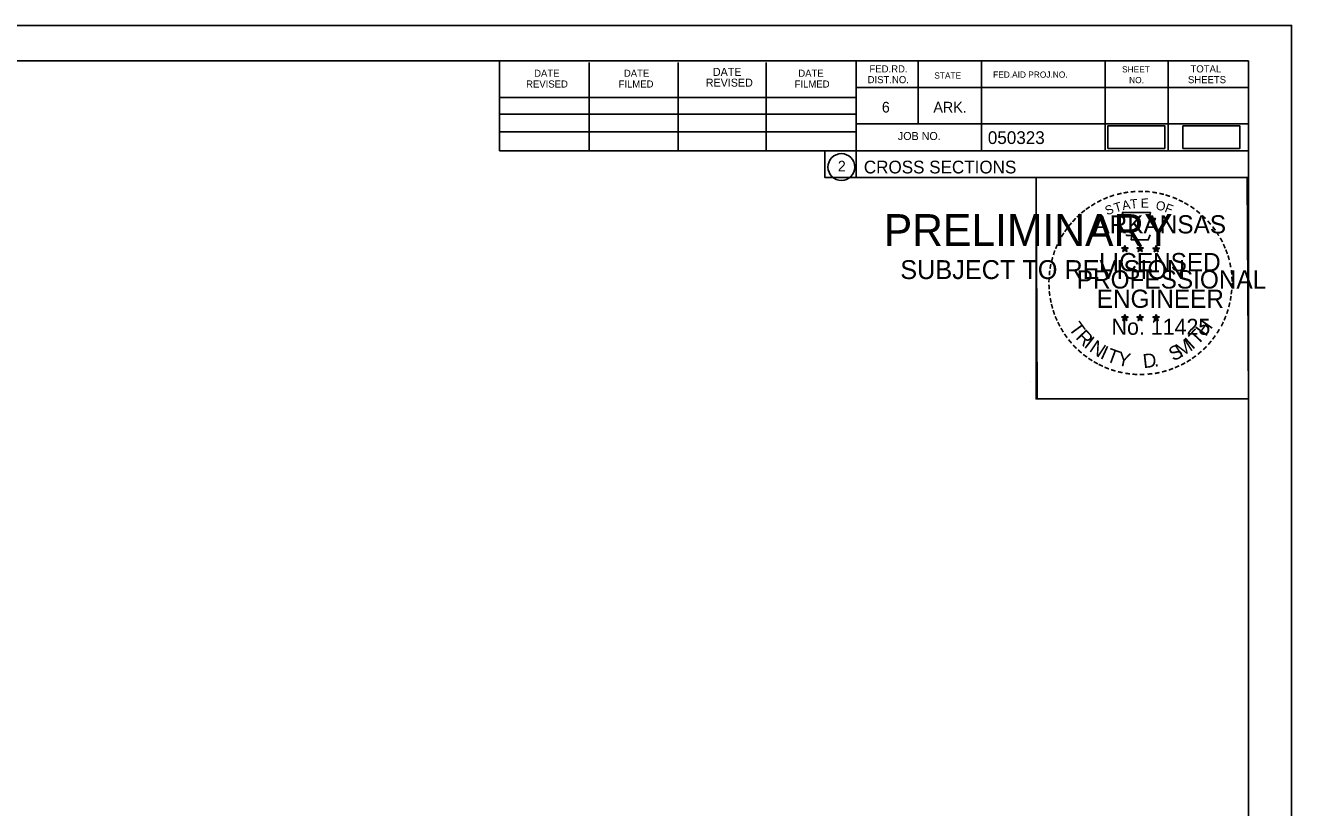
# Model space of a CAD drawing. Extents: x 1360146 to 1361431, y 631444 to 632352.
# Drawn here: x 1360340.6 to 1360479.7, y 632211.6 to 632297.5 of the extents above; entities that cross this region are included whole.
import ezdxf

# ---------------------------------------------------------------- set-up
doc = ezdxf.new("R2010")
doc.units = 0
for name, color, linetype in [('Default', 7, 'Continuous'), ('R_Border', 7, 'Continuous'), ('R_Border PE', 7, 'Continuous'), ('R_Border Prem', 7, 'Continuous'), ('R_No Plot', 7, 'Continuous')]:
    doc.layers.add(name, color=color, linetype=linetype)

msp = doc.modelspace()

# ---------------------------------------------------------------- linework, layer by layer
at = {"layer": 'Default'}
for points in [[(1360459.52, 632284), (1360465.77, 632284), (1360465.77, 632286.48), (1360459.52, 632286.48)], [(1360467.76, 632283.99), (1360474.01, 632283.99), (1360474.01, 632286.46), (1360467.76, 632286.46)]]:
    msp.add_lwpolyline(points, close=True, dxfattribs=at)
at = {"layer": 'R_Border'}
for p, q in [((1360158.77, 632293.62), (1360474.95, 632293.62)), ((1360392.69, 632283.74), (1360392.69, 632293.62)), ((1360431.85, 632293.62), (1360431.85, 632280.82)), ((1360438.69, 632293.62), (1360438.69, 632286.68)), ((1360445.63, 632293.62), (1360445.63, 632283.74)), ((1360459.21, 632293.62), (1360459.21, 632283.74)), ((1360466.15, 632293.62), (1360466.15, 632283.74)), ((1360474.95, 632088.16), (1360474.95, 632293.62)), ((1360402.55, 632283.74), (1360402.55, 632293.42)), ((1360412.31, 632283.74), (1360412.31, 632293.42)), ((1360421.99, 632283.74), (1360421.99, 632293.42)), ((1360392.69, 632289.6), (1360431.85, 632289.6)), ((1360474.95, 632290.68), (1360431.85, 632290.68)), ((1360474.95, 632290.7), (1360474.95, 632290.7)), ((1360392.69, 632287.74), (1360431.85, 632287.74)), ((1360474.95, 632286.68), (1360431.85, 632286.68)), ((1360434.81, 632286.68), (1360474.95, 632286.68)), ((1360392.69, 632283.74), (1360392.69, 632285.8)), ((1360392.69, 632285.8), (1360431.85, 632285.8)), ((1360474.95, 632283.74), (1360392.69, 632283.74)), ((1360431.85, 632280.82), (1360474.95, 632280.82))]:
    msp.add_line(p, q, dxfattribs=at)
msp.add_circle((1360430.24, 632281.95), 1.47, dxfattribs=at)
at = {"layer": 'R_Border PE'}
for p, q in [((1360461.04, 632273.07), (1360461.38, 632272.96)), ((1360461.04, 632273.07), (1360461.29, 632273.03)), ((1360461.04, 632273.07), (1360461.27, 632272.95)), ((1360461.17, 632272.67), (1360461.38, 632272.96)), ((1360461.17, 632272.67), (1360461.29, 632272.91)), ((1360461.17, 632272.67), (1360461.38, 632272.88)), ((1360461.38, 632273.33), (1360461.34, 632273.08)), ((1360461.38, 632272.96), (1360461.38, 632273.33)), ((1360461.38, 632273.33), (1360461.43, 632273.08)), ((1360461.73, 632273.07), (1360461.38, 632272.96)), ((1360461.6, 632272.67), (1360461.38, 632272.96)), ((1360461.6, 632272.67), (1360461.38, 632272.88)), ((1360461.73, 632273.07), (1360461.45, 632273.02)), ((1360461.6, 632272.67), (1360461.46, 632272.96)), ((1360461.73, 632273.07), (1360461.53, 632272.97)), ((1360462.71, 632273.07), (1360463.05, 632272.96)), ((1360462.71, 632273.07), (1360462.96, 632273.03)), ((1360462.71, 632273.07), (1360462.94, 632272.95)), ((1360462.84, 632272.67), (1360463.05, 632272.96)), ((1360462.84, 632272.67), (1360462.96, 632272.91)), ((1360462.84, 632272.67), (1360463.05, 632272.88)), ((1360463.05, 632273.33), (1360463.01, 632273.08)), ((1360463.05, 632272.96), (1360463.05, 632273.33)), ((1360463.05, 632273.33), (1360463.1, 632273.08)), ((1360463.4, 632273.07), (1360463.05, 632272.96)), ((1360463.27, 632272.67), (1360463.05, 632272.96)), ((1360463.27, 632272.67), (1360463.05, 632272.88)), ((1360463.4, 632273.07), (1360463.12, 632273.02)), ((1360463.27, 632272.67), (1360463.13, 632272.96)), ((1360463.4, 632273.07), (1360463.2, 632272.97)), ((1360464.47, 632273.06), (1360464.82, 632272.95)), ((1360464.47, 632273.06), (1360464.72, 632273.02)), ((1360464.47, 632273.06), (1360464.71, 632272.94)), ((1360464.6, 632272.65), (1360464.82, 632272.95)), ((1360464.6, 632272.65), (1360464.73, 632272.9)), ((1360464.6, 632272.65), (1360464.82, 632272.87)), ((1360464.82, 632273.32), (1360464.78, 632273.06)), ((1360464.82, 632272.95), (1360464.82, 632273.32)), ((1360464.82, 632273.32), (1360464.87, 632273.07)), ((1360465.17, 632273.06), (1360464.82, 632272.95)), ((1360465.03, 632272.65), (1360464.82, 632272.95)), ((1360465.03, 632272.65), (1360464.82, 632272.87)), ((1360465.17, 632273.06), (1360464.88, 632273.01)), ((1360465.03, 632272.65), (1360464.89, 632272.94)), ((1360465.17, 632273.06), (1360464.96, 632272.96)), ((1360461.03, 632265.5), (1360461.38, 632265.39)), ((1360461.03, 632265.5), (1360461.28, 632265.46)), ((1360461.03, 632265.5), (1360461.27, 632265.38)), ((1360461.16, 632265.09), (1360461.38, 632265.39)), ((1360461.16, 632265.09), (1360461.29, 632265.34)), ((1360461.16, 632265.09), (1360461.38, 632265.31)), ((1360461.38, 632265.75), (1360461.34, 632265.5)), ((1360461.38, 632265.39), (1360461.38, 632265.75)), ((1360461.38, 632265.75), (1360461.43, 632265.5)), ((1360461.73, 632265.5), (1360461.38, 632265.39)), ((1360461.59, 632265.09), (1360461.38, 632265.39)), ((1360461.59, 632265.09), (1360461.38, 632265.31)), ((1360461.73, 632265.5), (1360461.44, 632265.45)), ((1360461.59, 632265.09), (1360461.46, 632265.38)), ((1360461.73, 632265.5), (1360461.52, 632265.4)), ((1360462.7, 632265.5), (1360463.05, 632265.39)), ((1360462.7, 632265.5), (1360462.95, 632265.46)), ((1360462.7, 632265.5), (1360462.94, 632265.38)), ((1360462.83, 632265.09), (1360463.05, 632265.39)), ((1360462.83, 632265.09), (1360462.96, 632265.34)), ((1360462.83, 632265.09), (1360463.05, 632265.31)), ((1360463.05, 632265.75), (1360463.01, 632265.5)), ((1360463.05, 632265.39), (1360463.05, 632265.75)), ((1360463.05, 632265.75), (1360463.1, 632265.5)), ((1360463.4, 632265.5), (1360463.05, 632265.39)), ((1360463.26, 632265.09), (1360463.05, 632265.39)), ((1360463.26, 632265.09), (1360463.05, 632265.31)), ((1360463.4, 632265.5), (1360463.11, 632265.45)), ((1360463.26, 632265.09), (1360463.13, 632265.38)), ((1360463.4, 632265.5), (1360463.19, 632265.4)), ((1360464.47, 632265.49), (1360464.82, 632265.38)), ((1360464.47, 632265.49), (1360464.72, 632265.45)), ((1360464.47, 632265.49), (1360464.7, 632265.37)), ((1360464.6, 632265.08), (1360464.82, 632265.38)), ((1360464.6, 632265.08), (1360464.73, 632265.33)), ((1360464.6, 632265.08), (1360464.81, 632265.3)), ((1360464.82, 632265.74), (1360464.78, 632265.49)), ((1360465.03, 632265.08), (1360464.81, 632265.3)), ((1360464.82, 632265.38), (1360464.82, 632265.74)), ((1360464.82, 632265.74), (1360464.87, 632265.49)), ((1360465.16, 632265.49), (1360464.82, 632265.38)), ((1360465.03, 632265.08), (1360464.82, 632265.38)), ((1360465.16, 632265.49), (1360464.88, 632265.44)), ((1360465.03, 632265.08), (1360464.89, 632265.37)), ((1360465.16, 632265.49), (1360464.96, 632265.39))]:
    msp.add_line(p, q, dxfattribs=at)
for points in [[(1360461.08, 632276.95), (1360461.35, 632276.12)], [(1360464.59, 632276.03), (1360464.73, 632276.31), (1360464.04, 632276.29), (1360464.19, 632276.95), (1360461.08, 632276.95)], [(1360461.57, 632274.53), (1360461.57, 632274.44), (1360462.13, 632274.42), (1360462.08, 632273.95), (1360463.95, 632273.95), (1360464.15, 632274.49)], [(1360461.38, 632273.33), (1360461.6, 632272.67), (1360461.04, 632273.07), (1360461.73, 632273.07), (1360461.17, 632272.67), (1360461.38, 632273.33)], [(1360463.05, 632273.33), (1360463.27, 632272.67), (1360462.71, 632273.07), (1360463.4, 632273.07), (1360462.84, 632272.67), (1360463.05, 632273.33)], [(1360464.82, 632273.32), (1360465.03, 632272.65), (1360464.47, 632273.06), (1360465.17, 632273.06), (1360464.6, 632272.65), (1360464.82, 632273.32)], [(1360461.38, 632265.75), (1360461.59, 632265.09), (1360461.03, 632265.5), (1360461.73, 632265.5), (1360461.16, 632265.09), (1360461.38, 632265.75)], [(1360463.05, 632265.75), (1360463.26, 632265.09), (1360462.7, 632265.5), (1360463.4, 632265.5), (1360462.83, 632265.09), (1360463.05, 632265.75)], [(1360464.82, 632265.74), (1360465.03, 632265.08), (1360464.47, 632265.49), (1360465.16, 632265.49), (1360464.6, 632265.08), (1360464.82, 632265.74)]]:
    msp.add_lwpolyline(points, dxfattribs=at)
for centre, radius in [((1360461.38, 632272.96), 0.172), ((1360461.38, 632272.96), 0.145), ((1360461.38, 632272.96), 0.116), ((1360461.38, 632272.96), 0.0991), ((1360461.38, 632272.96), 0.0747), ((1360461.38, 632272.96), 0.0495), ((1360461.38, 632272.96), 0.0296), ((1360463.05, 632272.96), 0.172), ((1360463.05, 632272.96), 0.145), ((1360463.05, 632272.96), 0.116), ((1360463.05, 632272.96), 0.0991), ((1360463.05, 632272.96), 0.0747), ((1360463.05, 632272.96), 0.0495), ((1360463.05, 632272.96), 0.0296), ((1360464.82, 632272.95), 0.172), ((1360464.82, 632272.95), 0.145), ((1360464.82, 632272.95), 0.116), ((1360464.82, 632272.95), 0.0991), ((1360464.82, 632272.95), 0.0747), ((1360464.82, 632272.95), 0.0495), ((1360464.82, 632272.95), 0.0296), ((1360461.38, 632265.39), 0.172), ((1360461.38, 632265.39), 0.145), ((1360461.38, 632265.39), 0.116), ((1360461.38, 632265.39), 0.0991), ((1360461.38, 632265.39), 0.0747), ((1360461.38, 632265.39), 0.0495), ((1360461.38, 632265.39), 0.0296), ((1360463.05, 632265.39), 0.172), ((1360463.05, 632265.39), 0.145), ((1360463.05, 632265.39), 0.116), ((1360463.05, 632265.39), 0.0991), ((1360463.05, 632265.39), 0.0747), ((1360463.05, 632265.39), 0.0495), ((1360463.05, 632265.39), 0.0296), ((1360464.82, 632265.38), 0.172), ((1360464.82, 632265.38), 0.145), ((1360464.82, 632265.38), 0.116), ((1360464.82, 632265.38), 0.0991), ((1360464.82, 632265.38), 0.0747), ((1360464.82, 632265.38), 0.0495), ((1360464.82, 632265.38), 0.0296)]:
    msp.add_circle(centre, radius, dxfattribs=at)
at = {"layer": 'R_No Plot'}
for p, q in [((1360146.37, 632297.51), (1360479.7, 632297.51)), ((1360450.99, 632258.36), (1360450.99, 632258.36))]:
    msp.add_line(p, q, dxfattribs=at)
for points in [[(1360146.36, 632297.51), (1360479.7, 632297.51), (1360479.7, 632084.17), (1360146.36, 632084.17)], [(1360392.69, 632293.62), (1360392.69, 632283.74), (1360428.42, 632283.74), (1360428.42, 632280.82), (1360451.62, 632280.82), (1360451.62, 632256.49), (1360474.95, 632256.49), (1360474.95, 632088.16), (1360158.77, 632088.16), (1360158.77, 632293.62)], [(1360451.62, 632280.82), (1360474.83, 632280.82), (1360474.95, 632256.49), (1360451.74, 632256.49)]]:
    msp.add_lwpolyline(points, close=True, dxfattribs=at)

# ---------------------------------------------------------------- texts
at = {"layer": 'R_Border'}
for s, height, p in [('DATE', 0.782, (1360396.49, 632291.86)), ('DATE', 0.782, (1360406.35, 632291.86)), ('DATE', 0.879, (1360416.13, 632291.96)), ('DATE', 0.782, (1360425.51, 632291.86)), ('FED.RD.', 0.782, (1360433.33, 632292.34)), ('STATE', 0.684, (1360440.45, 632291.66)), ('FED.AID PROJ.NO.', 0.684, (1360446.91, 632291.76)), ('SHEET', 0.684, (1360461.07, 632292.34)), ('TOTAL', 0.782, (1360468.59, 632292.34)), ('REVISED', 0.782, (1360395.61, 632290.68)), ('FILMED', 0.782, (1360405.77, 632290.68)), ('REVISED', 0.879, (1360415.35, 632290.78)), ('FILMED', 0.782, (1360425.11, 632290.68)), ('DIST.NO.', 0.782, (1360433.13, 632291.16)), ('NO.', 0.684, (1360461.85, 632291.16)), ('SHEETS', 0.782, (1360468.31, 632291.16)), ('6', 1.17, (1360434.69, 632287.94)), ('ARK.', 1.172, (1360440.35, 632287.94)), ('JOB NO.', 0.879, (1360436.45, 632284.92)), ('050323', 1.4, (1360446.33, 632284.48)), ('2', 1.17, (1360429.85, 632281.47)), ('CROSS SECTIONS', 1.4, (1360432.71, 632281.25))]:
    msp.add_text(s, height=height, rotation=360, dxfattribs=at).set_placement(p)
at = {"layer": 'R_Border PE'}
for s, height, rotation, p in [('-', 1.6, 28.7918, (1360458.56, 632277.49)), ('-', 1.6, 24.3072, (1360459.19, 632277.81)), ('-', 1.6, 19.1761, (1360459.82, 632278.08)), ('-', 1.6, 13.6301, (1360460.57, 632278.32)), ('A', 1, 11.2132, (1360461.17, 632277.21)), ('-', 1.6, 10.2193, (1360461.25, 632278.48)), ('T', 1, 6.0228, (1360462.02, 632277.38)), ('-', 1.6, 5.8968, (1360461.98, 632278.59)), ('-', 1.6, 0.1862, (1360462.75, 632278.66)), ('E', 1, 0.8323, (1360463.13, 632277.49)), ('-', 1.6, 357.743, (1360463.48, 632278.65)), ('-', 1.6, 352.1617, (1360464.22, 632278.59)), ('-', 1.6, 347.2049, (1360464.94, 632278.48)), ('-', 1.6, 342.3362, (1360465.57, 632278.33)), ('-', 1.6, 337.8551, (1360466.31, 632278.1)), ('-', 1.6, 334.1211, (1360466.94, 632277.83)), ('-', 1.6, 38.9507, (1360456.91, 632276.35)), ('-', 1.6, 36.2317, (1360457.38, 632276.73)), ('-', 1.6, 34.0636, (1360457.96, 632277.12)), ('S', 1, 21.594, (1360459.43, 632276.63)), ('T', 1, 16.4036, (1360460.35, 632276.96)), ('O', 1, 350.4515, (1360464.73, 632277.28)), ('F', 1, 340.0707, (1360465.68, 632277.05)), ('-', 1.6, 329.6409, (1360467.52, 632277.55)), ('-', 1.6, 325.8627, (1360468.16, 632277.19)), ('-', 1.6, 320.5297, (1360468.77, 632276.76)), ('-', 1.6, 50.6142, (1360455.62, 632274.97)), ('-', 1.6, 48.423, (1360456.03, 632275.45)), ('-', 1.6, 42.9622, (1360456.47, 632275.93)), ('ARKANSAS', 2, 360, (1360457.93, 632274.66)), ('-', 1.6, 315.5786, (1360469.37, 632276.27)), ('-', 1.6, 309.8797, (1360469.94, 632275.72)), ('-', 1.6, 62.8713, (1360454.57, 632273.26)), ('-', 1.6, 58.0706, (1360454.88, 632273.87)), ('-', 1.6, 54.2325, (1360455.21, 632274.4)), ('-', 1.6, 306.6522, (1360470.47, 632275.12)), ('-', 1.4, 303.6753, (1360470.95, 632274.55)), ('-', 1.6, 299.6684, (1360471.27, 632273.95)), ('-', 1.6, 72.3945, (1360454.09, 632272.02)), ('-', 1.6, 67.7743, (1360454.31, 632272.65)), ('DWB', 0.01, 360, (1360461.37, 632272.96)), ('DWB', 0.01, 360, (1360463.04, 632272.96)), ('DWB', 0.01, 360, (1360464.81, 632272.95)), ('-', 1.6, 294.6628, (1360471.59, 632273.33)), ('-', 1.6, 290.5728, (1360471.85, 632272.76)), ('-', 1.6, 75.461, (1360453.9, 632271.31)), ('LICENSED', 2, 360, (1360458.53, 632270.51)), ('-', 1.6, 285.1233, (1360472.09, 632272.18)), ('-', 1.6, 280.5493, (1360472.29, 632271.44)), ('-', 1.6, 85.1863, (1360453.69, 632269.9)), ('-', 1.6, 81.2013, (1360453.76, 632270.59)), ('PROFESSIONAL', 2, 360, (1360456.1, 632268.61)), ('-', 1.6, 276.5962, (1360472.45, 632270.67)), ('-', 1.6, 94.1959, (1360453.7, 632268.48)), ('-', 1.6, 89.0622, (1360453.66, 632269.2)), ('-', 1.6, 274.3301, (1360472.51, 632269.95)), ('-', 1.6, 269.9407, (1360472.54, 632269.31)), ('-', 1.6, 98.9479, (1360453.77, 632267.81)), ('-', 1.6, 101.7149, (1360453.91, 632267.08)), ('ENGINEER', 2, 360, (1360458.29, 632266.49)), ('-', 1.6, 260.9953, (1360472.45, 632267.99)), ('-', 1.6, 263.5172, (1360472.52, 632268.65)), ('-', 1.6, 105.4578, (1360454.07, 632266.48)), ('-', 1.6, 109.0874, (1360454.28, 632265.85)), ('-', 1.6, 252.8681, (1360472.16, 632266.6)), ('-', 1.6, 255.7626, (1360472.34, 632267.32)), ('-', 1.6, 114.0643, (1360454.54, 632265.25)), ('-', 1.6, 115.7289, (1360454.84, 632264.64)), ('T', 1.54, 306.0406, (1360455.14, 632264.23)), ('No. 11425', 1.757, 360, (1360459.92, 632263.53)), ('DWB', 0.01, 360, (1360461.37, 632265.38)), ('DWB', 0.01, 360, (1360463.04, 632265.38)), ('DWB', 0.01, 360, (1360464.8, 632265.37)), ('H', 1.54, 54.6088, (1360470.26, 632263.26)), ('-', 1.6, 244.6197, (1360471.68, 632265.29)), ('-', 1.6, 247.8887, (1360471.94, 632265.92)), ('-', 1.6, 120.4471, (1360455.2, 632264.05)), ('-', 1.6, 125.8934, (1360455.6, 632263.49)), ('-', 1.6, 130.7181, (1360456.06, 632262.94)), ('R', 1.54, 314.005, (1360455.9, 632263.18)), ('I', 1.54, 321.9694, (1360456.8, 632262.25)), ('M', 1.54, 32.6563, (1360467.52, 632260.99)), ('I', 1.54, 42.1136, (1360468.81, 632261.84)), ('T', 1.54, 46.6444, (1360469.37, 632262.32)), ('-', 1.6, 233.8452, (1360470.88, 632263.89)), ('-', 1.6, 239.0712, (1360471.28, 632264.54)), ('-', 1.6, 134.2238, (1360456.58, 632262.39)), ('-', 1.6, 138.9338, (1360457.11, 632261.93)), ('N', 1.54, 326.5002, (1360457.37, 632261.78)), ('I', 1.54, 335.3603, (1360458.58, 632260.99)), ('T', 1.54, 339.8912, (1360459.24, 632260.66)), ('Y', 1.54, 347.8556, (1360460.46, 632260.22)), ('S', 1.54, 26.9312, (1360466.69, 632260.59)), ('-', 1.6, 221.0851, (1360469.45, 632262.25)), ('-', 1.6, 225.7653, (1360469.97, 632262.76)), ('-', 1.6, 231.2538, (1360470.45, 632263.32)), ('-', 1.6, 144.6463, (1360457.66, 632261.52)), ('-', 1.6, 148.0898, (1360458.22, 632261.15)), ('-', 1.6, 151.5704, (1360458.8, 632260.83)), ('-', 1.6, 154.6002, (1360459.32, 632260.58)), ('D', 1.54, 6.3969, (1360463.44, 632259.86)), ('.', 1.54, 13.7642, (1360464.63, 632259.99)), ('-', 1.6, 204.2516, (1360467.18, 632260.73)), ('-', 1.6, 207.3568, (1360467.81, 632261.04)), ('-', 1.6, 212.2491, (1360468.37, 632261.39)), ('-', 1.6, 215.7363, (1360468.9, 632261.78)), ('-', 1.6, 158.5612, (1360459.95, 632260.32)), ('-', 1.6, 162.7983, (1360460.63, 632260.11)), ('-', 1.6, 167.5555, (1360461.35, 632259.95)), ('-', 1.6, 173.1155, (1360462.12, 632259.84)), ('-', 1.6, 176.5183, (1360462.87, 632259.78)), ('-', 1.6, 181.5918, (1360463.61, 632259.8)), ('-', 1.6, 185.8167, (1360464.42, 632259.88)), ('-', 1.6, 191.2858, (1360465.16, 632260.01)), ('-', 1.6, 195.4743, (1360465.89, 632260.21)), ('-', 1.6, 200.7184, (1360466.56, 632260.45))]:
    msp.add_text(s, height=height, rotation=rotation, dxfattribs=at).set_placement(p)
at = {"layer": 'R_Border Prem'}
for s, height, p in [('PRELIMINARY', 3.5, (1360434.9, 632273.28)), ('DWB', 0.01, (1360435.65, 632275.13)), ('SUBJECT TO REVISION', 2.0751, (1360436.71, 632269.65))]:
    msp.add_text(s, height=height, rotation=360, dxfattribs=at).set_placement(p)

doc.saveas('drawing.dxf')
